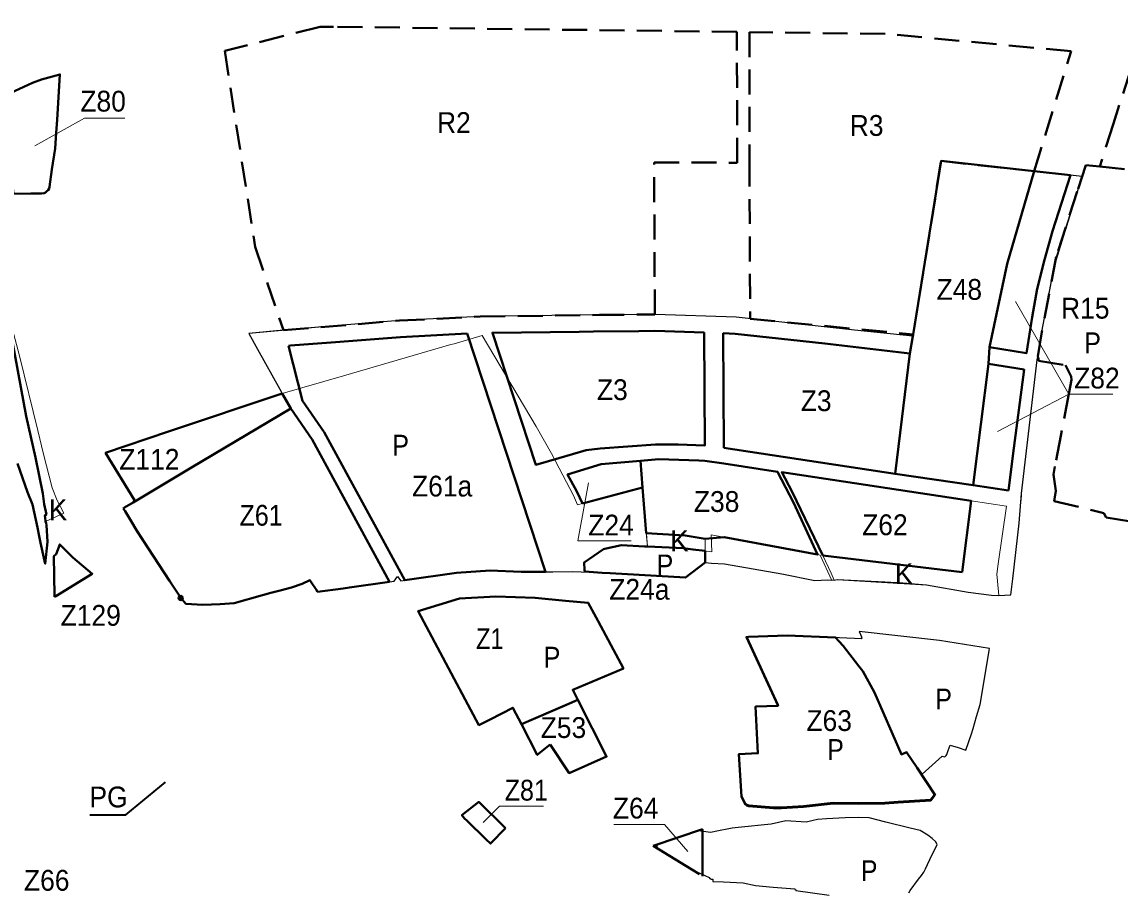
# Model space of a CAD drawing. Extents: x -650276 to -642489, y -1074311 to -1066658.
# Drawn here: x -647871 to -646603, y -1070195 to -1069193 of the extents above; entities that cross this region are included whole.
import ezdxf

# ---------------------------------------------------------------- set-up
doc = ezdxf.new("R2010")
doc.units = 0
doc.header["$LTSCALE"] = 9.6
doc.header["$PDMODE"] = 32
doc.header["$PDSIZE"] = 4.8
doc.linetypes.add('MEDIUM_DASHED', pattern=[4.5, 3, -1.5])
for name, color, linetype, lineweight in [('42', 7, 'Continuous', 25), ('44', 7, 'Continuous', 40), ('45', 7, 'Continuous', 40), ('46', 7, 'Continuous', 13), ('47', 7, 'Continuous', 13), ('48', 7, 'Continuous', 13), ('60', 7, 'Continuous', 35), ('61', 7, 'MEDIUM_DASHED', 40), ('62', 7, 'Continuous', 35), ('63', 7, 'Continuous', 13)]:
    doc.layers.add(name, color=color, linetype=linetype, lineweight=lineweight)

msp = doc.modelspace()

# ---------------------------------------------------------------- linework, layer by layer
at = {"layer": '42'}
for points in [[(-647235.49, -1069826.51), (-647205.603, -1069827.72), (-647191.66, -1069828.58), (-647201.106, -1069827.997), (-647191.66, -1069828.58), (-647104.741, -1069833.568), (-647082.145, -1069816.321), (-647074.72, -1069816.8), (-647060.029, -1069817.854), (-646993.81, -1069829.12), (-646993.81, -1069829.12), (-646955.45, -1069836.93), (-646940.94, -1069836.34), (-646933.39, -1069836.51), (-646929.67, -1069835.68), (-646826.63, -1069841.84), (-646778.74, -1069850.44), (-646751.8, -1069853.72), (-646743.31, -1069854.26), (-646729.54, -1069853.69), (-646727.09, -1069835.05), (-646719.79, -1069770.87), (-646716.98, -1069736.73), (-646698.96, -1069582.26), (-646698.96, -1069582.26), (-646698.4, -1069578.93), (-646693.58, -1069550.28), (-646679.13, -1069473.51), (-646647.141, -1069370.826), (-646702.425, -1069364.771), (-646809.879, -1069353.002), (-646842.103, -1069553.182), (-646842.441, -1069555.283), (-646910.029, -1069548.006), (-646986.633, -1069539.757), (-647046.325, -1069533.275), (-647140.008, -1069530.068), (-647204.293, -1069530.647), (-647341.697, -1069532.602), (-647434.969, -1069537.141), (-647523.931, -1069544.499), (-647568.792, -1069548.21), (-647608.81, -1069551.868), (-647598.735, -1069570.026), (-647573.15, -1069616.16), (-647570.37, -1069621.18), (-647570.37, -1069621.18), (-647701.61, -1069665.279), (-647774.11, -1069689.64), (-647740.74, -1069744.24), (-647742.36, -1069746.93), (-647752.32, -1069752.95), (-647753.7, -1069753.9), (-647745.84, -1069766.71), (-647687.45, -1069857.15), (-647681.51, -1069863.72), (-647661.79, -1069864.92), (-647641.78, -1069864.26), (-647625.83, -1069863.19), (-647593.07, -1069853.74), (-647572.63, -1069848.63), (-647559.47, -1069844.92), (-647547.12, -1069840.87), (-647538.34, -1069836.68), (-647531.33, -1069847.23), (-647529.5, -1069849.99), (-647492.76, -1069845.02), (-647441.19, -1069837.6), (-647437.46, -1069832.27), (-647433.32, -1069837.33), (-647369.3, -1069828.22), (-647330.46, -1069825.51), (-647294.38, -1069826.88)], [(-647294.38, -1069826.88), (-647270.09, -1069827.02), (-647258.143, -1069827.094), (-647235.49, -1069826.51)], [(-646901.388, -1069904.174), (-646987.56, -1069900.52), (-647032.16, -1069902.13), (-647033.853, -1069902.188)], [(-647033.853, -1069902.188), (-646998.06, -1069980.039), (-646998.716, -1069980.064)], [(-646753.995, -1069915.425), (-646811.935, -1069906.155), (-646904.446, -1069895.991), (-646901.388, -1069902.723), (-646902.06, -1069902.694), (-646901.388, -1069904.174)], [(-646831.912, -1070060.406), (-646808.49, -1070039.689), (-646805.65, -1070040.439), (-646803.87, -1070038.879), (-646803.43, -1070037.629), (-646801.84, -1070033.139), (-646799.45, -1070026.749), (-646790.27, -1070029.749), (-646781.39, -1070032.779), (-646774.86, -1070014.019), (-646772.96, -1070007.579), (-646768.91, -1069993.979), (-646764.81, -1069980.189), (-646757.45, -1069936.669), (-646754.36, -1069917.669), (-646753.995, -1069915.425)], [(-646998.716, -1069980.064), (-646998.06, -1069981.49), (-647023.975, -1069982.477)], [(-647023.975, -1069982.477), (-647021.27, -1070034.829), (-647021.345, -1070034.832)], [(-647021.345, -1070034.832), (-647021.27, -1070036.28), (-647043.157, -1070037.286)], [(-647043.157, -1070037.286), (-647040.12, -1070084.659), (-647036.03, -1070093.509), (-647034.17, -1070095.039), (-647031.73, -1070095.759), (-647003.49, -1070098.209), (-646993.92, -1070098.039), (-646968.89, -1070096.569), (-646934.63, -1070092.789), (-646904.97, -1070093.069)], [(-646904.97, -1070093.069), (-646874.9, -1070092.649), (-646859.29, -1070091.649), (-646821.89, -1070089.249), (-646817.427, -1070083.656), (-646831.912, -1070061.857), (-646831.305, -1070061.32), (-646831.912, -1070060.406)], [(-646847.17, -1070197.38), (-646845.76, -1070194.67), (-646836.06, -1070181.31), (-646832.62, -1070177.08), (-646829.87, -1070173.61), (-646827.95, -1070169.52), (-646820.51, -1070153.68), (-646814.53, -1070141.96), (-646816.06, -1070138.5), (-646820.35, -1070134.43), (-646825.4, -1070130.78), (-646834.04, -1070125.34), (-646845.78, -1070122.84), (-646873.5, -1070115.8), (-646892.87, -1070110.82), (-646904.66, -1070110.24), (-646920.68, -1070110.58), (-646941.99, -1070111.74), (-646952.66, -1070112.57), (-646965.6, -1070115.74), (-646989.24, -1070114.17), (-646989.24, -1070114.17), (-647005.97, -1070117.89), (-647044.19, -1070121.78), (-647051.14, -1070122.49), (-647070.7, -1070126.64), (-647075.81, -1070127.72), (-647090.2, -1070125.64), (-647133.96, -1070140.44), (-647136.65, -1070141.75), (-647137.99, -1070143.09), (-647137.96, -1070144.66), (-647136.09, -1070146.97), (-647132.95, -1070149.08), (-647097.63, -1070170.37), (-647077.39, -1070179.57), (-647076.83, -1070180.73), (-647075.42, -1070181.53), (-647073.42, -1070181.47), (-647073.35, -1070184.01), (-647061.2, -1070184.6), (-647038.31, -1070185.73), (-647024.2, -1070188.68), (-647003.89, -1070190.89), (-646978.73, -1070192.54), (-646978.72, -1070193.6), (-646977.7, -1070193.62), (-646977.7, -1070194.45), (-646938.98, -1070199.89)]]:
    msp.add_lwpolyline(points, dxfattribs=at)
at = {"layer": '44'}
msp.add_line((-646772.907, -1069727.177), (-646732.143, -1069733.308), dxfattribs=at)
for points in [[(-647860.52, -1069390.72), (-647848.24, -1069390.65), (-647845.25, -1069390.07), (-647843.41, -1069389.23), (-647841.81, -1069387.99), (-647840.42, -1069386.51), (-647839.4, -1069384.73), (-647838.79, -1069382.86), (-647836.2, -1069362.68), (-647832.29, -1069338.58), (-647832.29, -1069338.58), (-647831.19, -1069320.69), (-647830.23, -1069305.38), (-647826.928, -1069253.199), (-647848.17, -1069259.21), (-647858.37, -1069263.03), (-647893.553, -1069279.017), (-647880.326, -1069390.832)], [(-646660.526, -1069369.36), (-646702.425, -1069364.771), (-646733.74, -1069471.688), (-646754.066, -1069567.993), (-646711.442, -1069574.759), (-646704.68, -1069533.06), (-646699.07, -1069500.57), (-646690.51, -1069466.97), (-646681.5, -1069434.17)], [(-647312.485, -1070122.583), (-647329.932, -1070140.465), (-647334.81, -1070135.73), (-647357.4, -1070113.69), (-647359.8, -1070111.34), (-647362.87, -1070107.74), (-647343.454, -1070092.368)]]:
    msp.add_lwpolyline(points, close=True, dxfattribs=at)
at = {"layer": '44', "lineweight": 13}
for points in [[(-647751.811, -1069303.761), (-647798.61, -1069303.761), (-647856.005, -1069335.572)], [(-647751.811, -1069303.761), (-647798.61, -1069303.761), (-647856.005, -1069335.572)], [(-646611.673, -1069622.045), (-646662.372, -1069622.045), (-646744.747, -1069664.938), (-646662.372, -1069622.045), (-646723.996, -1069515.165)], [(-647268.839, -1070097.432), (-647319.538, -1070097.432), (-647338.315, -1070116.223)], [(-647268.839, -1070097.432), (-647319.538, -1070097.432), (-647338.315, -1070116.223)]]:
    msp.add_lwpolyline(points, dxfattribs=at)
at = {"layer": '44'}
for points in [[(-647865.69, -1069647.32), (-647887.649, -1069528.021), (-647887.087, -1069527.229)], [(-646725.82, -1069684.5), (-646714.037, -1069593.585), (-646755.269, -1069587.04), (-646772.907, -1069727.177)], [(-647842.438, -1069760.647), (-647845.086, -1069748.753), (-647846.484, -1069736.663), (-647855.158, -1069695.232), (-647865.69, -1069647.32)], [(-646732.143, -1069733.308), (-646725.82, -1069684.5), (-646725.82, -1069684.5)], [(-647875.82, -1069701.85), (-647864.19, -1069735.12), (-647858.44, -1069749.43), (-647852.63, -1069775.7), (-647850.66, -1069785.74), (-647849.165, -1069793.367), (-647843.74, -1069817.63), (-647841.402, -1069792.351)], [(-647841.402, -1069792.351), (-647842.489, -1069773.282), (-647842.622, -1069770.956), (-647843.337, -1069769.013), (-647843.443, -1069768.293), (-647843.458, -1069768.256), (-647843.449, -1069768.252), (-647844.371, -1069761.991), (-647842.438, -1069760.647)]]:
    msp.add_lwpolyline(points, dxfattribs=at)
at = {"layer": '45'}
for p, q in [((-647085.131, -1070123.926), (-647142.227, -1070143.236)), ((-647085.131, -1070123.926), (-647142.227, -1070143.236)), ((-647085.131, -1070177.975), (-647085.131, -1070123.926)), ((-647085.131, -1070177.975), (-647085.131, -1070123.926))]:
    msp.add_line(p, q, dxfattribs=at)
for points in [[(-646842.441, -1069555.283), (-646842.103, -1069553.182), (-646809.879, -1069353.002), (-646702.425, -1069364.771), (-646702.425, -1069364.771), (-646702.425, -1069364.771), (-646702.425, -1069364.771), (-646702.425, -1069364.771), (-646733.74, -1069471.688), (-646733.74, -1069471.688), (-646754.066, -1069567.993)], [(-646842.441, -1069555.283), (-646842.103, -1069553.182), (-646809.879, -1069353.002), (-646702.425, -1069364.771), (-646702.425, -1069364.771), (-646702.425, -1069364.771), (-646702.425, -1069364.771), (-646702.425, -1069364.771), (-646733.74, -1069471.688), (-646733.74, -1069471.688), (-646754.066, -1069567.993)], [(-647356.899, -1069552.034), (-647433.779, -1069556.106), (-647433.779, -1069556.106), (-647513.66, -1069562.249), (-647514.067, -1069562.282), (-647560.836, -1069566.036), (-647563.104, -1069566.28)], [(-647369.3, -1069828.22), (-647330.46, -1069825.51), (-647294.38, -1069826.88), (-647270.09, -1069827.02), (-647266.581, -1069827.042), (-647356.899, -1069552.034)], [(-647563.104, -1069566.28), (-647546.777, -1069629.901), (-647521.943, -1069665.763)], [(-646754.066, -1069567.993), (-646755.269, -1069587.04), (-646772.906, -1069727.176), (-646863, -1069714), (-646846, -1069575), (-646842.441, -1069555.283)], [(-646754.066, -1069567.993), (-646755.269, -1069587.04), (-646772.906, -1069727.176), (-646863, -1069714), (-646846, -1069575), (-646842.441, -1069555.283)], [(-647570.37, -1069621.18), (-647701.61, -1069665.279), (-647774.11, -1069689.64), (-647740.74, -1069744.24), (-647742.36, -1069746.93), (-647674.901, -1069706.701)], [(-647570.37, -1069621.18), (-647701.61, -1069665.279), (-647774.11, -1069689.64), (-647740.74, -1069744.24), (-647742.36, -1069746.93), (-647674.901, -1069706.701)], [(-647674.901, -1069706.701), (-647560.36, -1069638.39), (-647570.37, -1069621.18)], [(-647674.901, -1069706.701), (-647560.36, -1069638.39), (-647570.37, -1069621.18)], [(-647560.36, -1069638.39), (-647674.901, -1069706.701), (-647742.36, -1069746.93)], [(-647446.322, -1069838.338), (-647535.588, -1069674.163), (-647560.36, -1069638.39)], [(-647521.943, -1069665.763), (-647428.993, -1069836.714), (-647369.3, -1069828.22)], [(-647742.36, -1069746.93), (-647752.32, -1069752.95), (-647753.7, -1069753.9)], [(-647753.7, -1069753.9), (-647751.66, -1069757.12), (-647745.84, -1069766.71), (-647737.17, -1069780.85), (-647700.58, -1069837.2), (-647687.45, -1069857.15), (-647681.51, -1069863.72)], [(-647641.78, -1069864.26), (-647625.83, -1069863.19), (-647593.07, -1069853.74), (-647583.62, -1069851.13), (-647572.63, -1069848.63), (-647559.47, -1069844.92), (-647547.12, -1069840.87), (-647538.34, -1069836.68), (-647536.82, -1069838.87), (-647531.33, -1069847.23), (-647529.5, -1069849.99), (-647500.03, -1069846.28), (-647492.76, -1069845.02), (-647446.322, -1069838.338)], [(-647681.51, -1069863.72), (-647661.79, -1069864.92), (-647641.78, -1069864.26)], [(-647142.227, -1070143.236), (-647097.63, -1070170.37), (-647088.916, -1070175.672)], [(-647142.227, -1070143.236), (-647097.63, -1070170.37), (-647088.916, -1070175.672)]]:
    msp.add_lwpolyline(points, dxfattribs=at)
for points in [[(-647251.002, -1069695.852), (-647219.628, -1069686.746), (-647203.374, -1069684.716), (-647139.649, -1069679.961), (-647113.255, -1069679.966), (-647082.761, -1069681.399), (-647083.356, -1069551.018), (-647140.247, -1069549.071), (-647158.572, -1069549.252), (-647211.05, -1069549.77), (-647227.623, -1069550.23), (-647327.682, -1069551.263), (-647277.71, -1069703.421)], [(-647251.002, -1069695.852), (-647219.628, -1069686.746), (-647203.374, -1069684.716), (-647139.649, -1069679.961), (-647113.255, -1069679.966), (-647082.761, -1069681.399), (-647083.356, -1069551.018), (-647140.247, -1069549.071), (-647158.572, -1069549.252), (-647211.05, -1069549.77), (-647227.623, -1069550.23), (-647327.682, -1069551.263), (-647277.71, -1069703.421)], [(-647060.7, -1069683.894), (-647061.304, -1069551.773), (-647047.648, -1069552.245), (-646944.168, -1069563.743), (-646846, -1069575), (-646863, -1069714)], [(-647060.7, -1069683.894), (-647061.304, -1069551.773), (-647047.648, -1069552.245), (-646944.168, -1069563.743), (-646846, -1069575), (-646863, -1069714)], [(-647223.66, -1069748.26), (-647154.33, -1069729.69), (-647156.782, -1069698.901), (-647202.181, -1069702.678), (-647240.994, -1069714.513), (-647230.16, -1069734.42)], [(-647223.66, -1069748.26), (-647154.33, -1069729.69), (-647156.782, -1069698.901), (-647202.181, -1069702.678), (-647240.994, -1069714.513), (-647230.16, -1069734.42)], [(-647060.617, -1069702.116), (-647082.682, -1069698.791), (-647089.456, -1069698.579), (-647135.585, -1069697.137), (-647156.782, -1069698.901), (-647154.33, -1069729.69), (-647150.138, -1069782.334), (-647105.334, -1069785.168), (-647082.271, -1069788.81), (-647060.23, -1069786.932), (-646952.56, -1069807.13), (-646980.4, -1069746.98), (-646998.56, -1069711.443)], [(-646785.437, -1069827.534), (-646775.286, -1069745.022), (-646993.771, -1069712.163), (-646981.92, -1069734.86), (-646946.369, -1069808.291)], [(-646785.437, -1069827.534), (-646775.286, -1069745.022), (-646993.771, -1069712.163), (-646981.92, -1069734.86), (-646946.369, -1069808.291)], [(-647833.172, -1069855.944), (-647833.172, -1069855.944), (-647831.62, -1069854.99), (-647789.55, -1069829.12), (-647811.83, -1069810.39), (-647827.16, -1069795.32), (-647831.32, -1069806.56), (-647833.91, -1069808.91), (-647833.2, -1069854.15)], [(-647196.616, -1069800.068), (-647199.65, -1069800.69), (-647221.87, -1069816.21), (-647221.28, -1069824.74), (-647221.14, -1069826.761), (-647201.106, -1069827.997), (-647191.66, -1069828.58), (-647104.741, -1069833.568), (-647082.145, -1069816.321), (-647082.206, -1069802.916), (-647096.39, -1069801.15), (-647107.04, -1069799.84), (-647148.9, -1069797.88), (-647152.39, -1069797.7), (-647178.73, -1069796.4)], [(-647365.866, -1069857.774), (-647413.461, -1069872.442), (-647343.28, -1070003.81), (-647339.69, -1070001.95), (-647330.5, -1069997.19), (-647304.05, -1069983.79), (-647294.257, -1070002.745), (-647242.254, -1069980.33), (-647229.096, -1069974.658), (-647235, -1069963), (-647176.499, -1069938.333), (-647205.781, -1069883.796), (-647217.177, -1069862.57), (-647243.231, -1069860.34), (-647278.525, -1069857.002), (-647323.794, -1069855.468)], [(-647365.866, -1069857.774), (-647413.461, -1069872.442), (-647343.28, -1070003.81), (-647339.69, -1070001.95), (-647330.5, -1069997.19), (-647304.05, -1069983.79), (-647294.257, -1070002.745), (-647242.254, -1069980.33), (-647229.096, -1069974.658), (-647235, -1069963), (-647176.499, -1069938.333), (-647205.781, -1069883.796), (-647217.177, -1069862.57), (-647243.231, -1069860.34), (-647278.525, -1069857.002), (-647323.794, -1069855.468)], [(-647032.16, -1069902.13), (-647034.51, -1069902.21), (-646998.06, -1069981.49), (-647024.05, -1069982.48), (-647021.27, -1070036.28), (-647043.25, -1070037.29), (-647040.12, -1070086.11), (-647036.03, -1070094.96), (-647034.17, -1070096.49), (-647031.73, -1070097.21), (-647003.49, -1070099.66), (-646993.92, -1070099.49), (-646968.89, -1070098.02), (-646934.63, -1070094.24), (-646904.97, -1070094.52), (-646874.9, -1070094.1), (-646859.29, -1070093.1), (-646821.89, -1070090.7), (-646817.15, -1070084.76), (-646816.9, -1070084.45), (-646837.65, -1070053.22), (-646849.79, -1070035.17), (-646855.62, -1070037.66), (-646886.85, -1069966.26), (-646900.26, -1069941.64), (-646904.72, -1069935.84), (-646922.79, -1069912.31), (-646931.67, -1069902.89), (-646987.56, -1069900.52)], [(-647261.27, -1070026.12), (-647238.99, -1070059.05), (-647195.933, -1070040.107), (-647229.096, -1069974.658), (-647294.257, -1070002.745), (-647276, -1070038.08)], [(-647261.27, -1070026.12), (-647238.99, -1070059.05), (-647195.933, -1070040.107), (-647229.096, -1069974.658), (-647294.257, -1070002.745), (-647276, -1070038.08)]]:
    msp.add_lwpolyline(points, close=True, dxfattribs=at)
msp.add_point((-647687.45, -1069857.15), dxfattribs=at)
at = {"layer": '46'}
for points in [[(-647167.693, -1069791.112), (-647229.126, -1069791.112), (-647217.012, -1069724.439)], [(-647167.693, -1069791.112), (-647229.126, -1069791.112), (-647217.012, -1069724.439)], [(-647187.627, -1070118.571), (-647128.949, -1070118.571), (-647102.191, -1070149.577)], [(-647187.627, -1070118.571), (-647128.949, -1070118.571), (-647102.191, -1070149.577)]]:
    msp.add_lwpolyline(points, dxfattribs=at)
at = {"layer": '47'}
for p, q in [((-647150.141, -1069782.334), (-647148.9, -1069797.88)), ((-647107.04, -1069799.84), (-647096.39, -1069801.15))]:
    msp.add_line(p, q, dxfattribs=at)
msp.add_lwpolyline([(-647845.086, -1069748.753), (-647842.438, -1069760.647), (-647844.371, -1069761.991), (-647843.337, -1069769.013), (-647822.54, -1069759.29), (-647830, -1069744.7), (-647835.76, -1069730.01), (-647845.85, -1069691.2), (-647852.44, -1069664.03), (-647873.43, -1069577.87), (-647887.087, -1069527.229), (-647865.69, -1069647.32), (-647855.158, -1069695.232), (-647846.484, -1069736.663)], close=True, dxfattribs=at)
for points in [[(-646778.74, -1069850.44), (-646751.8, -1069853.72), (-646743.31, -1069854.26), (-646743.7, -1069850.07), (-646745.56, -1069829.84), (-646743.85, -1069817.72), (-646734.48, -1069751.35), (-646775.286, -1069745.022), (-646785.437, -1069827.534), (-646946.369, -1069808.291), (-646936.6, -1069828.47), (-646933.39, -1069836.51)], [(-647082.271, -1069788.81), (-647105.334, -1069785.168), (-647105.334, -1069785.168), (-647150.138, -1069782.334)], [(-647096.39, -1069801.15), (-647096.39, -1069801.15), (-647082.206, -1069802.917), (-647082.271, -1069788.81)], [(-647148.9, -1069797.88), (-647148.9, -1069797.88), (-647107.04, -1069799.84)], [(-646933.39, -1069836.51), (-646933.39, -1069836.51), (-646929.67, -1069835.68), (-646875, -1069838.65), (-646853.88, -1069839.8), (-646826.63, -1069841.84), (-646778.74, -1069850.44), (-646778.74, -1069850.44)]]:
    msp.add_lwpolyline(points, dxfattribs=at)
at = {"layer": '60'}
msp.add_lwpolyline([(-647792.254, -1070107.298), (-647750.945, -1070107.298), (-647704.94, -1070069.715)], dxfattribs=at)
msp.add_lwpolyline([(-647792.254, -1070107.298), (-647750.945, -1070107.298), (-647704.94, -1070069.715)], dxfattribs=at)
at = {"layer": '61'}
msp.add_line((-646626.774, -1069359.349), (-646642.89, -1069357.68), dxfattribs=at)
for points in [[(-646572.586, -1069194.485), (-646577.878, -1069206.485), (-646611.107, -1069309.68), (-646626.774, -1069359.349), (-646580.797, -1069364.111), (-646571.479, -1069363.822), (-646526.31, -1069184.381), (-646570.296, -1069190.776)], [(-647045.7, -1069204.106), (-647511.107, -1069198.223), (-647526.615, -1069198.093), (-647636.743, -1069226.014), (-647601.568, -1069452.14), (-647568.792, -1069548.21), (-647434.969, -1069537.141), (-647341.697, -1069532.602), (-647204.293, -1069530.647), (-647140.334, -1069530.057), (-647141.134, -1069354.872), (-647045.123, -1069355.003)], [(-647031.152, -1069204.288), (-647031.152, -1069353.712), (-647030.324, -1069535.053), (-646842.103, -1069553.182), (-646809.879, -1069353.002), (-646702.425, -1069364.771), (-646659.946, -1069226.375), (-646874.542, -1069206.4)]]:
    msp.add_lwpolyline(points, close=True, dxfattribs=at)
msp.add_lwpolyline([(-646642.89, -1069357.68), (-646652.72, -1069388.08), (-646677.18, -1069463.79), (-646693.58, -1069550.28), (-646698.4, -1069578.93), (-646697.31, -1069579.97), (-646697.31, -1069583.47), (-646666.36, -1069588.57), (-646659.83, -1069601.8), (-646659.52, -1069605.53), (-646662.57, -1069621.66), (-646671.69, -1069669.92), (-646678.52, -1069705.63), (-646680.28, -1069714.83), (-646677.36, -1069733.65), (-646679.46, -1069745.37), (-646622, -1069759.34), (-646619.49, -1069764.46), (-646585.51, -1069769.57), (-646583.457, -1069759.191), (-646548.91, -1069578.56), (-646580.797, -1069364.111)], dxfattribs=at)
at = {"layer": '63'}
for points in [[(-646647.141, -1069370.826), (-646660.526, -1069369.36), (-646702.425, -1069364.771), (-646809.879, -1069353.002), (-646819.59, -1069413.326), (-646842.103, -1069553.182), (-646842.441, -1069555.283), (-646910.029, -1069548.006), (-646986.633, -1069539.757), (-647046.325, -1069533.275), (-647140.008, -1069530.068), (-647204.293, -1069530.647), (-647341.697, -1069532.602), (-647434.969, -1069537.141), (-647523.931, -1069544.499), (-647608.81, -1069551.868)], [(-646729.54, -1069853.69), (-646728.21, -1069843.59), (-646727.09, -1069835.05), (-646719.79, -1069770.87), (-646719.27, -1069764.58), (-646717.8, -1069746.68), (-646717.19, -1069739.32), (-646716.98, -1069736.73), (-646698.96, -1069582.26), (-646698.4, -1069578.93), (-646694.47, -1069556.69), (-646693.58, -1069550.28), (-646686.56, -1069511.7), (-646680.77, -1069481.22), (-646679.13, -1069473.51), (-646677.18, -1069463.79), (-646664.07, -1069423.21), (-646652.72, -1069388.08), (-646647.141, -1069370.826)], [(-647608.81, -1069551.868), (-647606.53, -1069555.98), (-647600.89, -1069566.14), (-647573.15, -1069616.16), (-647570.37, -1069621.18), (-647499.63, -1069600.73), (-647375.71, -1069564.91), (-647371.83, -1069563.79), (-647339.58, -1069554.46), (-647277.43, -1069659.15), (-647259.62, -1069690.56), (-647246.42, -1069715.63), (-647234.25, -1069739.09), (-647229.389, -1069749.562), (-647223.66, -1069748.26), (-647154.33, -1069729.69), (-647152.73, -1069749.81), (-647151.57, -1069764.44), (-647148.9, -1069797.88), (-647107.04, -1069799.84), (-647096.39, -1069801.15), (-647074.31, -1069803.9), (-647075.22, -1069784.12), (-646952.56, -1069807.13)], [(-646952.56, -1069807.13), (-646949.48, -1069807.71), (-646936.08, -1069837.11), (-646933.39, -1069836.51), (-646929.67, -1069835.68), (-646875, -1069838.65), (-646853.88, -1069839.8), (-646826.63, -1069841.84), (-646778.74, -1069850.44), (-646751.8, -1069853.72), (-646743.31, -1069854.26), (-646729.54, -1069853.69)]]:
    msp.add_lwpolyline(points, dxfattribs=at)

# ---------------------------------------------------------------- texts
at = {"layer": '44'}
for s, width, p in [('Z80', 0.95, (-647803.311, -1069296.044)), ('Z80', 0.95, (-647803.311, -1069296.044)), ('Z82', 0.95, (-646656.364, -1069615.463)), ('Z81', 0.9, (-647313.531, -1070090.851)), ('Z81', 0.9, (-647313.531, -1070090.851))]:
    msp.add_text(s, height=24, dxfattribs=dict(at, width=width)).set_placement(p)
at = {"layer": '46'}
for s, width, p in [('Z48', 0.95, (-646815.179, -1069513.185)), ('Z48', 0.95, (-646815.179, -1069513.185)), ('Z3', 0.95, (-647207.094, -1069628.872)), ('Z3', 0.95, (-647207.094, -1069628.872)), ('Z3', 0.95, (-646971.871, -1069641.589)), ('Z3', 0.95, (-646971.871, -1069641.589)), ('Z112', 0.95, (-647758.383, -1069709.22)), ('Z112', 0.95, (-647758.383, -1069709.22)), ('Z61a', 0.95, (-647420.53, -1069740.066)), ('Z38', 0.95, (-647095.223, -1069757.854)), ('Z38', 0.95, (-647095.223, -1069757.854)), ('Z61', 0.9, (-647619.576, -1069773.738)), ('Z24', 0.95, (-647217.069, -1069785.057)), ('Z24', 0.95, (-647217.069, -1069785.057)), ('Z62', 0.95, (-646900.991, -1069784.684)), ('Z62', 0.95, (-646900.991, -1069784.684)), ('Z24a', 0.95, (-647192.847, -1069859.131)), ('Z129', 0.95, (-647826.051, -1069889.189)), ('Z1', 0.85, (-647346.649, -1069916.072)), ('Z1', 0.85, (-647346.649, -1069916.072)), ('Z53', 0.95, (-647272.017, -1070018.639)), ('Z53', 0.95, (-647272.017, -1070018.639)), ('Z63', 0.95, (-646965.327, -1070010.57)), ('Z64', 0.95, (-647188.663, -1070111.521)), ('Z64', 0.95, (-647188.663, -1070111.521)), ('Z66', 0.95, (-647868.376, -1070194.801))]:
    msp.add_text(s, height=24, dxfattribs=dict(at, width=width)).set_placement(p)
at = {"layer": '48'}
for p in [(-647839.874, -1069767.492), (-647122.713, -1069803.226), (-646863.536, -1069841.154)]:
    msp.add_text('K', height=24, dxfattribs=at).set_placement(p)
at = {"layer": '60'}
for s, width, p in [('P', 0.9, (-646644.717, -1069574.793)), ('P', 0.9, (-646644.717, -1069574.793)), ('P', 0.9, (-647443.274, -1069692.913)), ('P', 0.9, (-647443.274, -1069692.913)), ('P', 0.9, (-647138.27, -1069830.996)), ('P', 0.9, (-647138.27, -1069830.996)), ('P', 0.9, (-647268.59, -1069937.47)), ('P', 0.9, (-647268.59, -1069937.47)), ('P', 0.9, (-646816.629, -1069985.717)), ('P', 0.9, (-646816.629, -1069985.717)), ('P', 0.9, (-646941.403, -1070043.945)), ('P', 0.9, (-646941.403, -1070043.945)), ('PG', 0.95, (-647792.805, -1070098.685)), ('PG', 0.95, (-647792.805, -1070098.685)), ('P', 0.9, (-646902.585, -1070183.692)), ('P', 0.9, (-646902.585, -1070183.692))]:
    msp.add_text(s, height=24, dxfattribs=dict(at, width=width)).set_placement(p)
at = {"layer": '62', "width": 0.95}
for s, p in [('R2', (-647391.654, -1069320.724)), ('R2', (-647391.654, -1069320.724)), ('R3', (-646915.354, -1069324.087)), ('R3', (-646915.354, -1069324.087)), ('R15', (-646671.455, -1069534.875)), ('R15', (-646671.455, -1069534.875))]:
    msp.add_text(s, height=24, dxfattribs=at).set_placement(p)

doc.saveas('drawing.dxf')
